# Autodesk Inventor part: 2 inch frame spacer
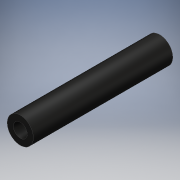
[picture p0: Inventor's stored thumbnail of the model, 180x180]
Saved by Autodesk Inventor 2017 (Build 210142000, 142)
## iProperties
Created: 2016-06
Part Number: 2 inch frame spacer
Material: Generic
Document SubType Name: Modeling
Designer: Stan
Density: 1 g/cm^3
Appearance: Glossy - Black
Author: Stan
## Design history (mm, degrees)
sketch "Sketch1"
  geometry: C1 r 2.54 at (0, 0); C2 r 4.763 at (0, 0); 1 further point
  constraints: 2 centre point, 2 coincident
  dimensions: "d0" = 9.525 diameter of C2; "d1" = 5.08 diameter of C1
extrude "Extrusion1" new body sketch "Sketch1" distance "d2" = 50.8; taper "d3" = 0 deg
body "Solid1"
